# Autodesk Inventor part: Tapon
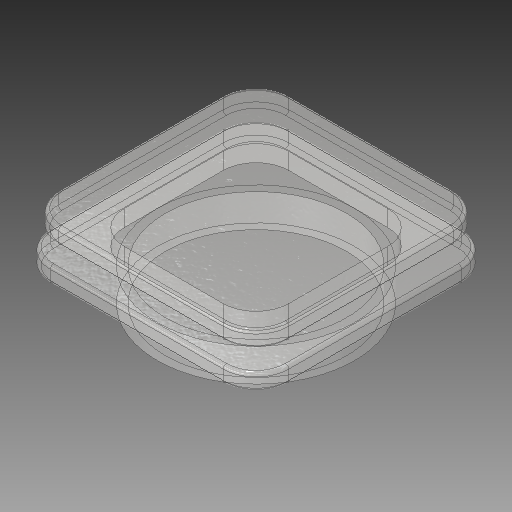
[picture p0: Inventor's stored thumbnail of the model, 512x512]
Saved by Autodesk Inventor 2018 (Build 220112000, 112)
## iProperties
Created: 2022-01
Part Number: Tapon
Material: Plástico, transparente
Document SubType Name: Modeling
Designer: Asus
Density: 1.188 g/cm^3
Appearance: Transparente - Claro
Mass: 629.934 g
Surface Area: 875.381 cm^2
Volume: 530.248 cm^3
Author: Asus
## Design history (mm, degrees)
sketch "Boceto1"
  geometry: L1 (72.5, 72.5)-(-72.5, 72.5); L2 (-72.5, 72.5)-(-72.5, -72.5); L3 (-72.5, -72.5)-(72.5, -72.5); L4 (72.5, -72.5)-(72.5, 72.5); L5 (72.5, 72.5)-(-72.5, -72.5); L6 (-72.5, 72.5)-(72.5, -72.5); C1 r 60 at (0, 0); C2 r 55 at (0, 0); 1 further point
  constraints: 12 end point, 2 centre point, 2 coincident, 2 midpoint, 2 parallel, 1 horizontal, 1 perpendicular
  dimensions: "d0" = 120 diameter of C1; "d1" = 110 diameter of C2; "d2" = 145 distance of L3.end L2.end; "d3" = 145 distance of L2.end L1.end
extrude "Extrusión1" new body sketch "Boceto1" distance "d4" = 20; taper "d5" = 0 deg
extrude "Extrusión2" join sketch "Boceto1" distance "d6" = 10; taper "d7" = 0 deg
sketch "Boceto2"
  geometry: L1 (50, -50)-(-50, -50); L2 (-50, -50)-(-50, 50); L3 (-50, 50)-(50, 50); L4 (50, 50)-(50, -50); L5 (50, -50)-(-50, 50); L6 (-50, -50)-(50, 50); 1 further point
  constraints: 12 end point, 2 midpoint, 2 parallel, 1 horizontal, 1 perpendicular
  dimensions: "d8" = 100 distance of L2.end L3.end; "d9" = 100 distance of L1.end L2.end
extrude "Extrusión3" join sketch "Boceto2" distance "d10" = 10; taper "d11" = 0 deg
sketch "Boceto3"
  geometry: L1 (70, -70)-(-70, -70); L2 (-70, -70)-(-70, 70); L3 (-70, 70)-(70, 70); L4 (70, 70)-(70, -70); L5 (70, -70)-(-70, 70); L6 (-70, -70)-(70, 70); 1 further point
  constraints: 12 end point, 2 midpoint, 2 parallel, 1 horizontal, 1 perpendicular
  dimensions: "d12" = 140 distance of L2.end L3.end; "d13" = 140 distance of L1.end L2.end
extrude "Extrusión4" join sketch "Boceto3" distance "d14" = 10; taper "d15" = 0 deg
fillet "Empalme1" dims "d16" = 20
fillet "Empalme2" dims "d17" = 2
node "Sólido1"
